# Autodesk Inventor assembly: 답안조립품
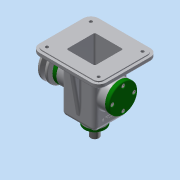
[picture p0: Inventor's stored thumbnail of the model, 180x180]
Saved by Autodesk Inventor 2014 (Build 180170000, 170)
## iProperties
Created: 2015-12
Part Number: 답안조립품
Document SubType Name: Assembly
Designer: Administrator
Author: Administrator
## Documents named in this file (19)
- D:\시험\답안조립품.iam
- D:\시험\본체.ipt
- D:\시험\편심축.ipt
- D:\시험\키 5 x 5 x 14.ipt
- D:\시험\V-벨트풀리.ipt
- D:\시험\와셔.ipt
- D:\시험\볼트 M6 x 12.ipt
- D:\시험\베어링 15 x 35 x 11.ipt
- D:\시험\멈춤링 15 x 1.ipt
- D:\시험\뒤커버.ipt
- D:\시험\볼트 M4 x 10.ipt
- D:\시험\앞커버.ipt
- D:\시험\슬라이드바.ipt
- D:\시험\링크.ipt
- D:\시험\고정핀.ipt
- D:\시험\멈춤링 6 x 5.ipt
- D:\시험\오일실 15 25 7.ipt
- D:\시험\상부부시.ipt
- D:\시험\볼트 M3 x 8.ipt
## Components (15 placed, 5 different names)
1. V-벨트풀리:1
2. ISO 4018 M6 x 12:1
3. 고정핀:1
4. ISO 4762 M4 x 10:1
5. ISO 4762 M4 x 10:2
6. ISO 4762 M4 x 10:3
7. ISO 4762 M4 x 10:4
8. ISO 4762 M4 x 10:5
9. ISO 4762 M4 x 10:6
10. ISO 4762 M4 x 10:7
11. ISO 4762 M4 x 10:8
12. ISO 4762 M3 x 8:1
13. ISO 4762 M3 x 8:2
14. ISO 4762 M3 x 8:3
15. ISO 4762 M3 x 8:4
